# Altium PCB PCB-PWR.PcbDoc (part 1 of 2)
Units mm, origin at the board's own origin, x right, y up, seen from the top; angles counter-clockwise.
Board outline 90 x 60 mm, 4 copper layers (F.Cu, In1.Cu, In2.Cu, B.Cu); 66 components, 31 nets, 210 pads, 267 vias.
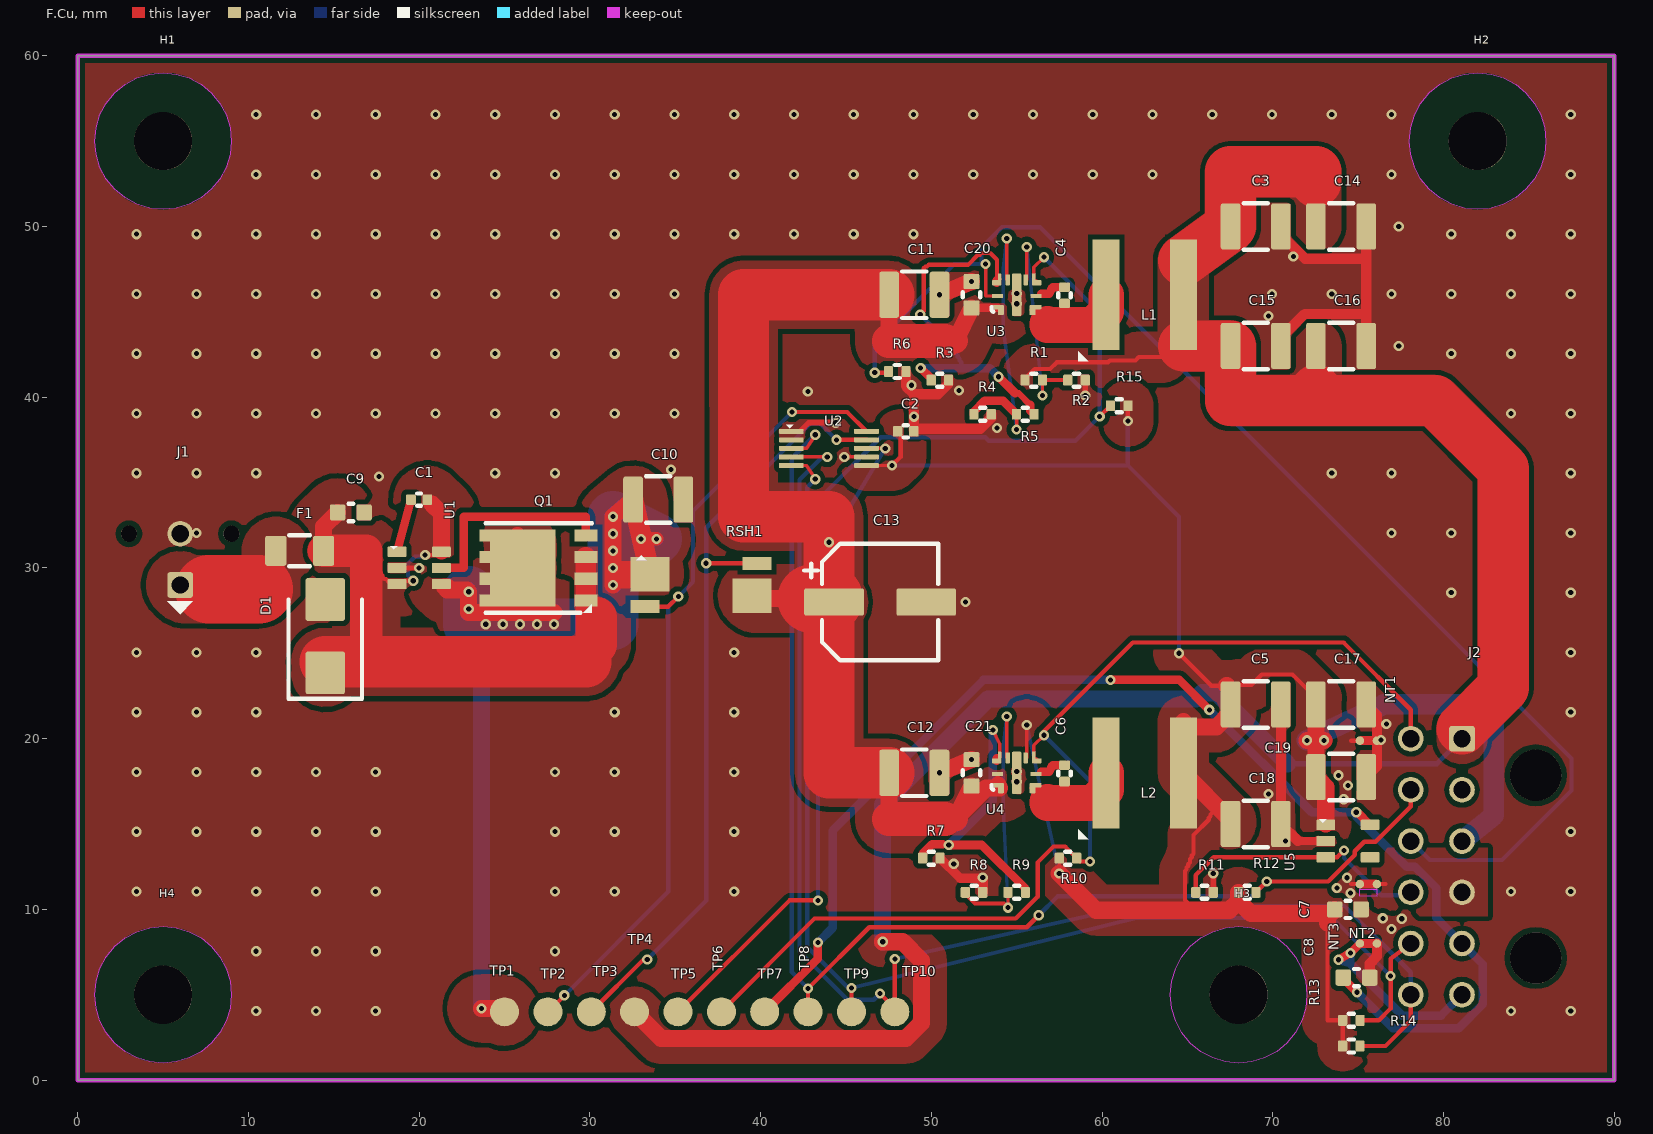
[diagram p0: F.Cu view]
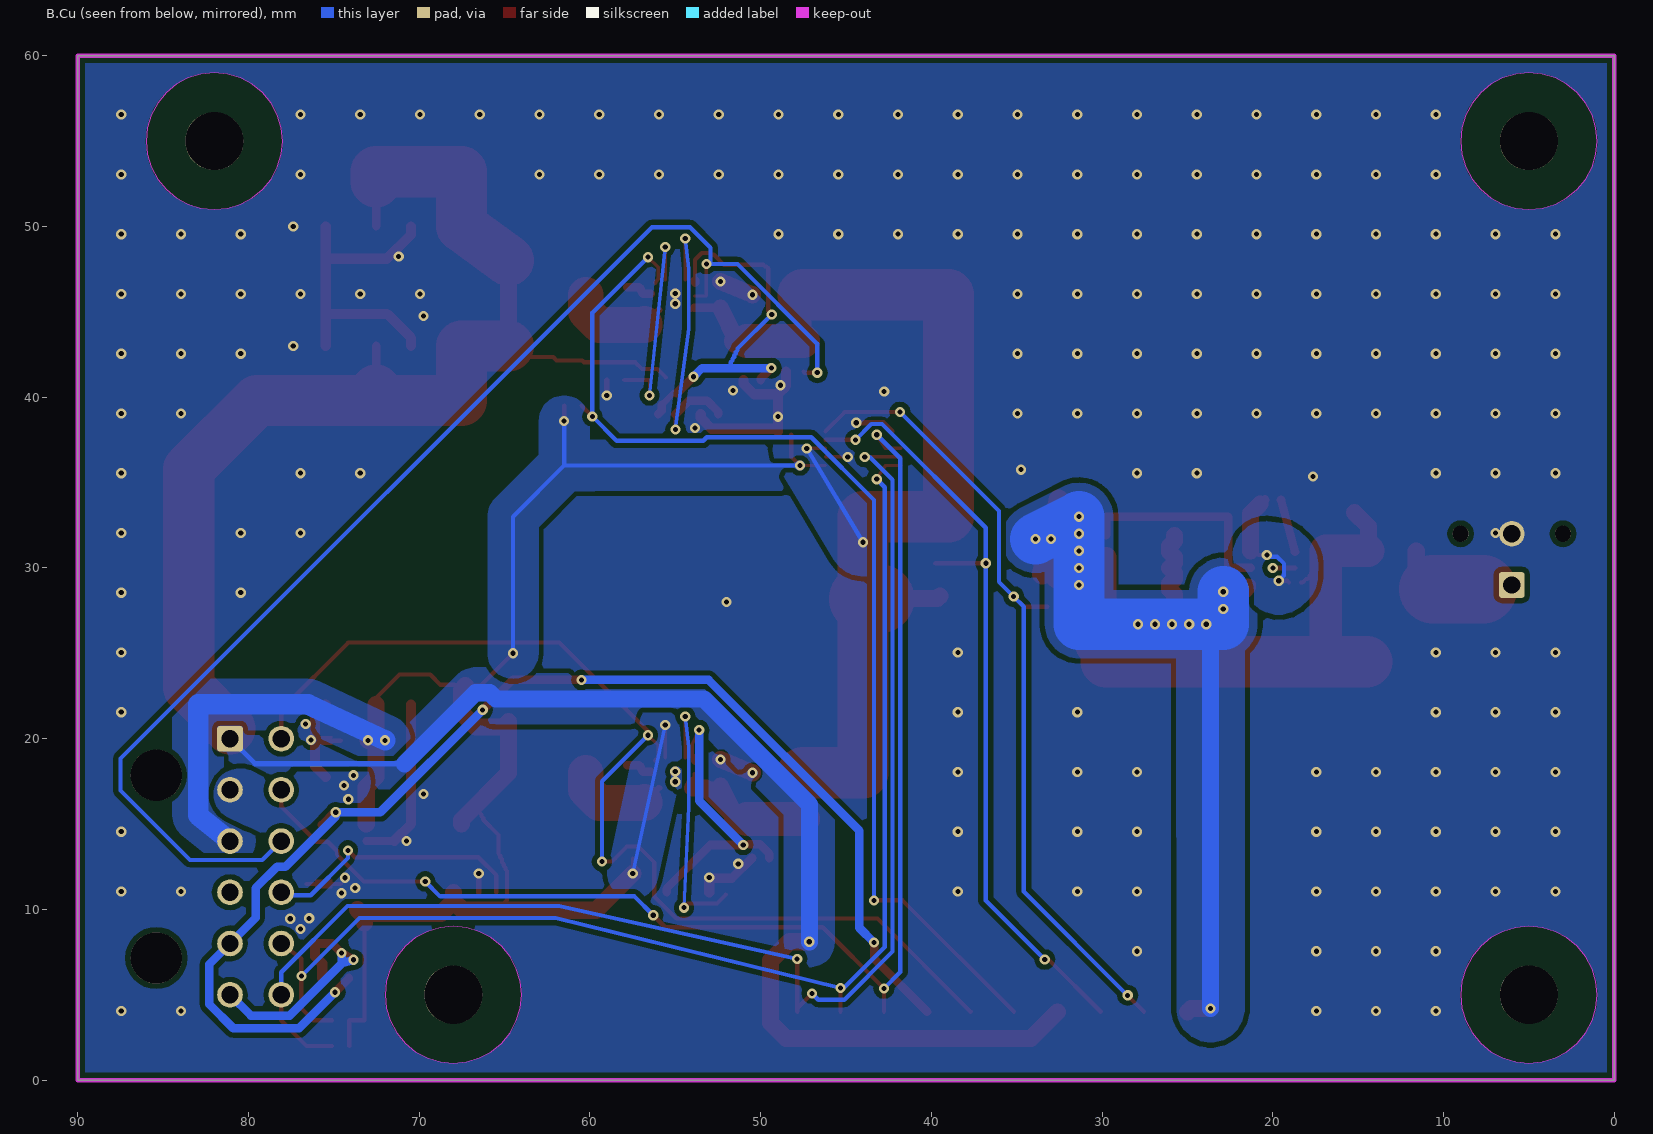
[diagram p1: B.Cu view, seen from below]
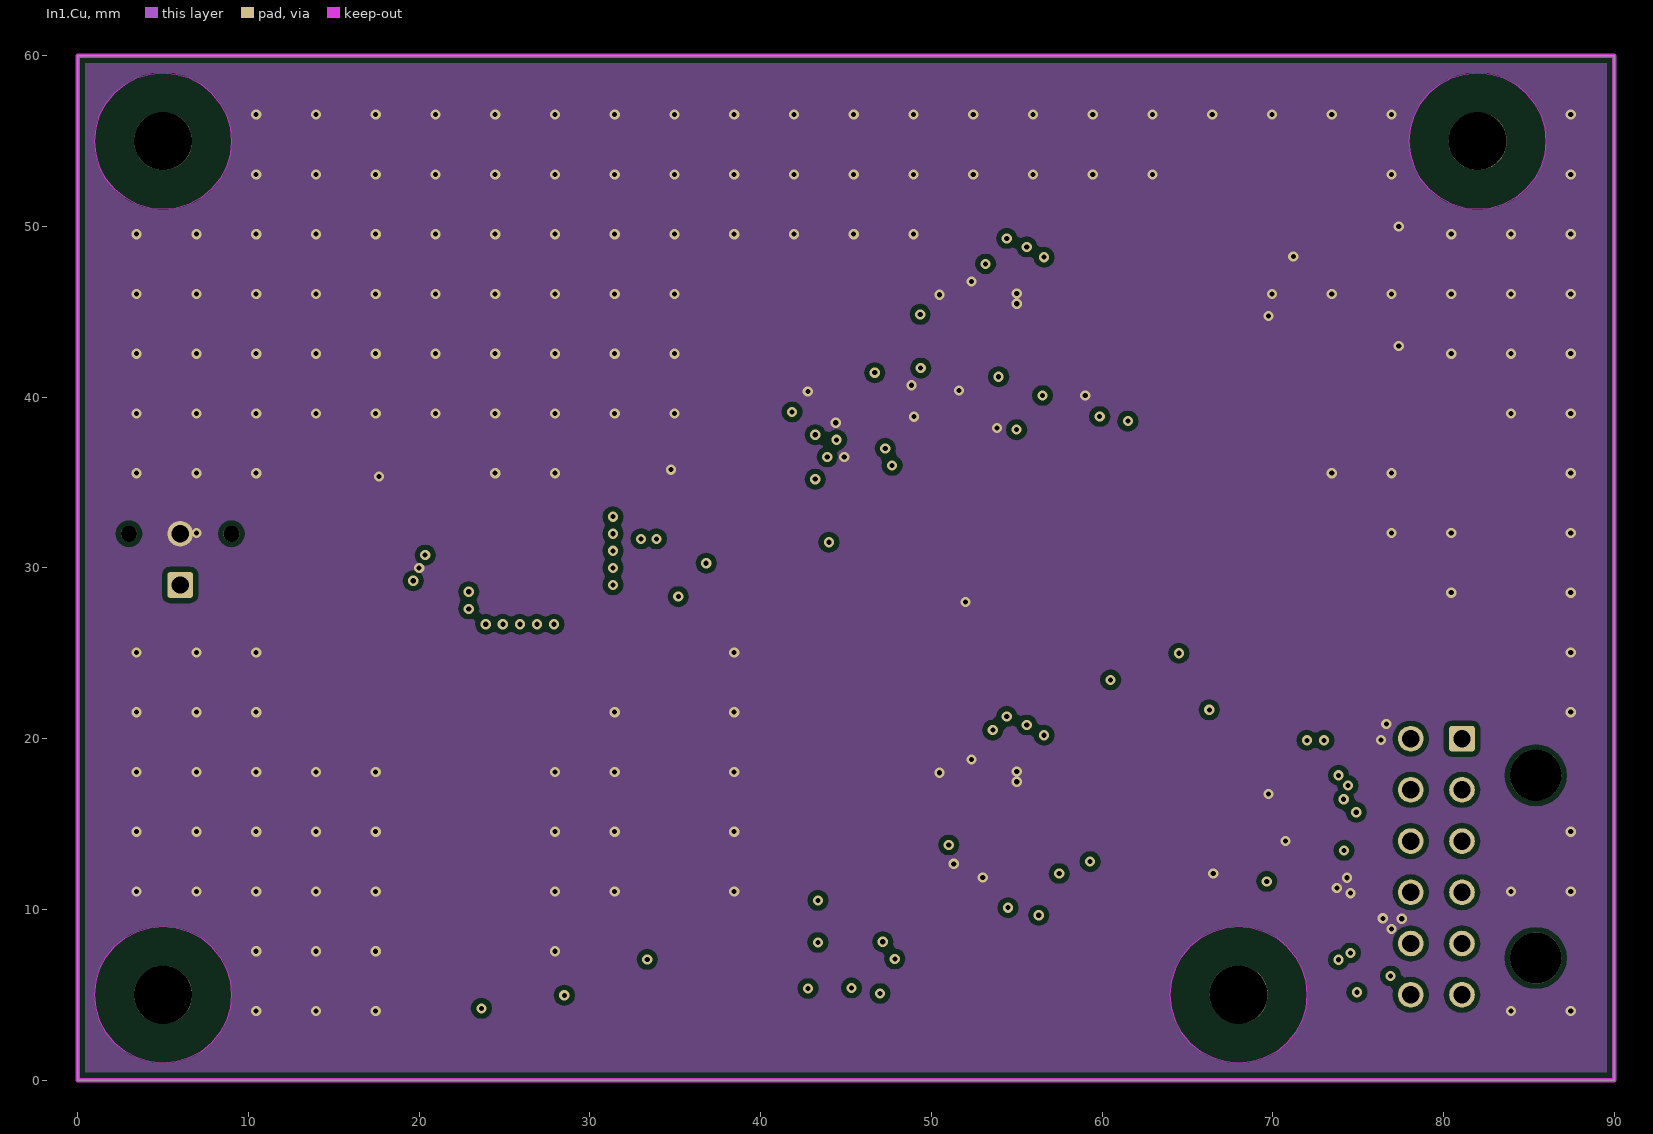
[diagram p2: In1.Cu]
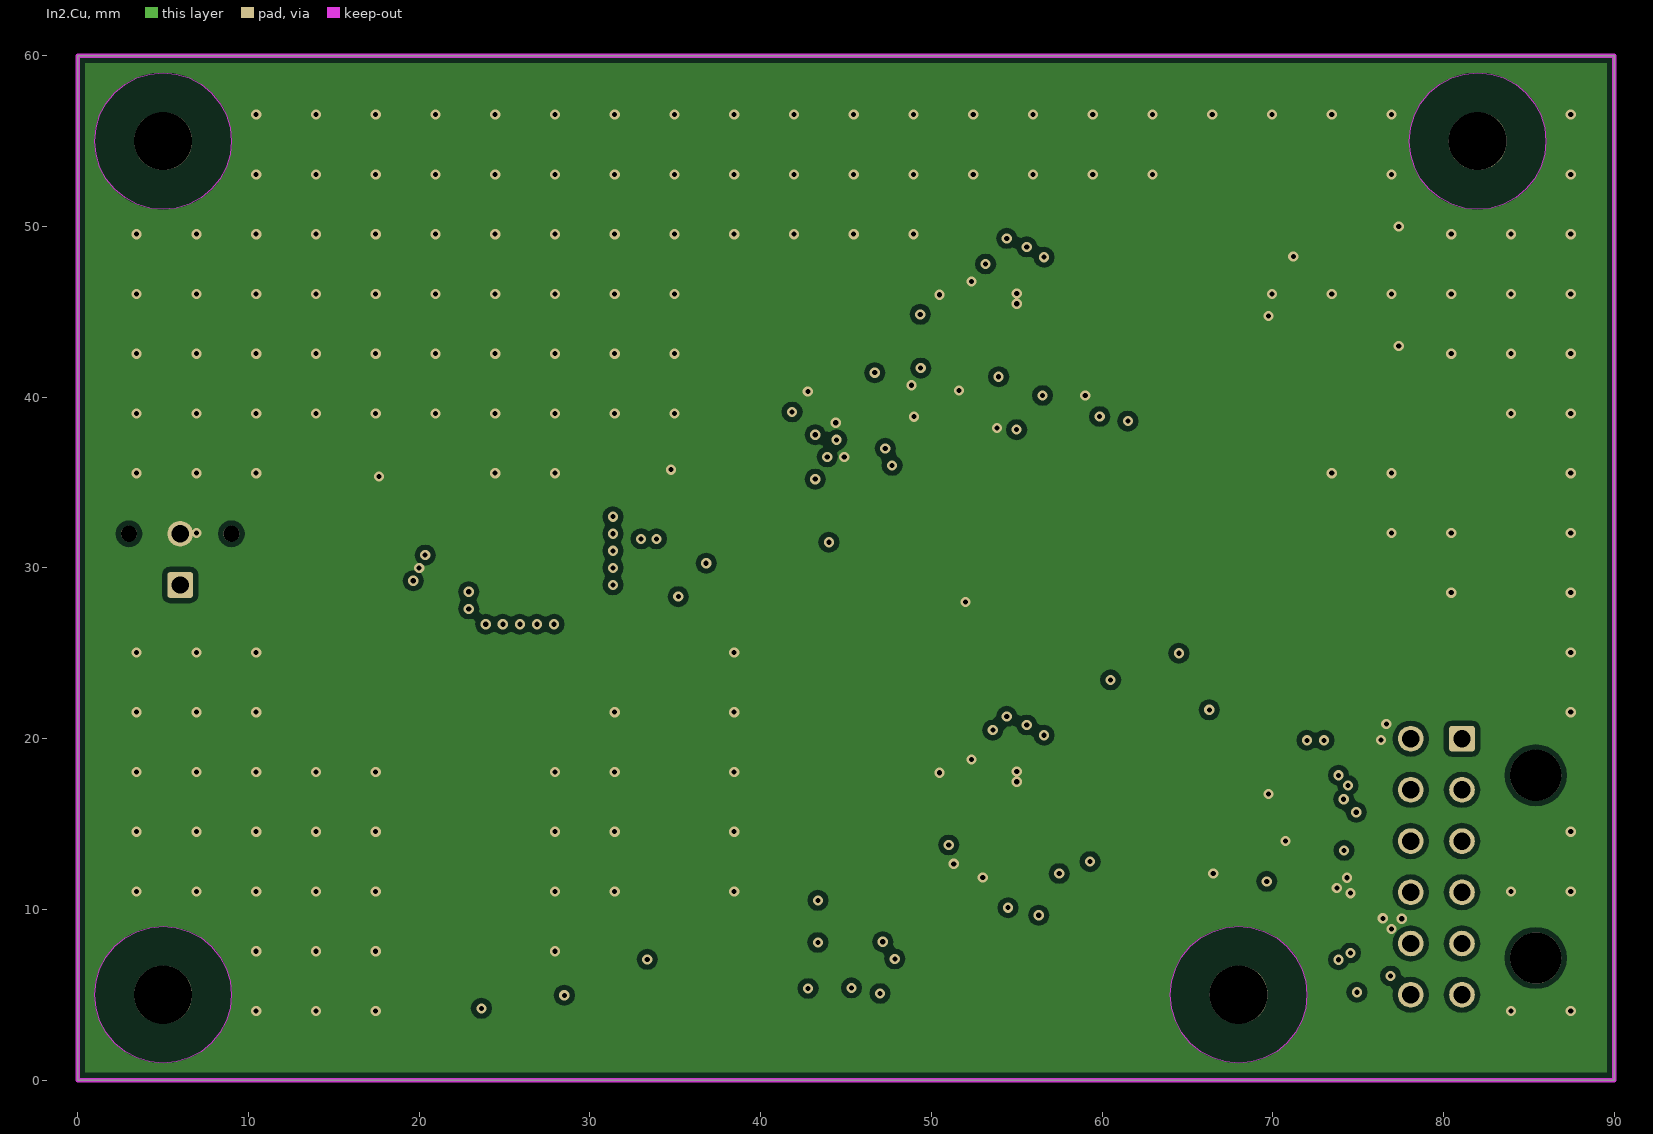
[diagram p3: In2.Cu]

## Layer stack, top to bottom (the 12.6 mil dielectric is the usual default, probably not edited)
F.Mask: solder mask 0.0102, Solder Resist, Dk 3.5
F.Cu: signal copper 0.0356
Dielectric 1: dielectric 0.32, FR-4, Dk 4.8
In1.Cu: signal copper 0.0356
Dielectric2: dielectric 0.32, FR-4, Dk 4.8
In2.Cu: signal copper 0.0356
Dielectric3: dielectric 0.32, FR-4, Dk 4.8
B.Cu: signal copper 0.0356
B.Mask: solder mask 0.0102, Solder Resist, Dk 3.5

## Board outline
0,0 0,60 90,60 90,0 0,0

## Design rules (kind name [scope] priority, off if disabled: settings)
Clearance "Clearence 2,3_PadClass" [InPadClass('Pad Class Clearance 2,3')] p1: gap=2.3 ignorepadtopadclearanceinfootprint=FALSE
Clearance "Clearence 0,3_Polygon" [InNamedPolygon('F.Cu-3V3_DIGITAL') OR InNamedPolygon('F.Cu-VBAT_SYS') OR InNamedPolygon('F.Cu-3V8_MODEM') OR InNamedPolygon('F.Cu-VBAT_PROTECTED') OR InNamedPolygon('F.Cu-VBAT_PROTECTED-1') OR InNamedPolygon('F.Cu-3V3_DIGITAL-1') OR InNamedPolygon('F.Cu-GND_MODEM') OR InNamedPolygon('F.Cu-3V3_DIGITAL-2') OR InNamedPolygon('F.Cu-GND_DIGITAL') OR InNamedPolygon('F.Cu-VBAT_FUSED') OR InNamedPolygon('F.Cu-3V8_MODEM-1') OR InNamedPolygon('F.Cu-GND_PWR') OR InNamedPolygon('F.Cu-3V3_DIGITAL-3') OR InNamedPolygon('F.Cu-VBAT_SYS-1') OR InNamedPolygon('F.Cu-VBAT_RAW') OR InNamedPolygon('B.Cu-3V3_DIGITAL') OR InNamedPolygon('B.Cu-3V3_DIGITAL-1') OR InNamedPolygon('B.Cu-GND_MODEM') OR InNamedPolygon('B.Cu-GND_PWR') OR InNamedPolygon('B.Cu-VBAT_PROTECTED') OR InNamedPolygon('B.Cu-VBAT_SYS') OR InNamedPolygon('B.Cu-3V8_MODEM') OR InNamedPolygon('B.Cu-3V3_DIGITAL-2') OR InNamedPolygon('B.Cu-VBAT_FUSED') OR InNamedPolygon('In1.Cu-GND_PWR') OR InNamedPolygon('In1.Cu-GND_PWR-1') OR InNamedPolygon('In1.Cu-GND_PWR-2') OR InNamedPolygon('In2.Cu-GND_PWR')] p2: gap=0.3 ignorepadtopadclearanceinfootprint=FALSE
HoleSize [All] p1: absolutevalues=TRUE maxlimit=3.4 minlimit=0.025 maxpercent=80.000 minpercent=20.000
MinimumSolderMaskSliver [All] p1: minsoldermaskwidth=0
PolygonConnect Polygon_In2.Cu-GND_PWR_ConnectDirect [IsNamedPolygon('In2.Cu-GND_PWR')] p1: connectstyle=Direct reliefconductorwidth=0.254 reliefentries=4 polygonreliefangle="90 Angle" airgapwidth=0.254
PolygonConnect Polygon_In1.Cu-GND_PWR-2_ConnectDirect [IsNamedPolygon('In1.Cu-GND_PWR-2')] p2: connectstyle=Direct reliefconductorwidth=0.254 reliefentries=4 polygonreliefangle="90 Angle" airgapwidth=0.254
PolygonConnect Polygon_In1.Cu-GND_PWR-1_ConnectDirect [IsNamedPolygon('In1.Cu-GND_PWR-1')] p3: connectstyle=Direct reliefconductorwidth=0.254 reliefentries=4 polygonreliefangle="90 Angle" airgapwidth=0.254
PolygonConnect Polygon_In1.Cu-GND_PWR_ConnectDirect [IsNamedPolygon('In1.Cu-GND_PWR')] p4: connectstyle=Direct reliefconductorwidth=0.254 reliefentries=4 polygonreliefangle="90 Angle" airgapwidth=0.254
PolygonConnect Polygon_B.Cu-VBAT_FUSED_ConnectDirect [IsNamedPolygon('B.Cu-VBAT_FUSED')] p5: connectstyle=Direct reliefconductorwidth=0.254 reliefentries=4 polygonreliefangle="90 Angle" airgapwidth=0.254
PolygonConnect Polygon_B.Cu-3V3_DIGITAL-2_ConnectDirect [IsNamedPolygon('B.Cu-3V3_DIGITAL-2')] p6: connectstyle=Direct reliefconductorwidth=0.254 reliefentries=4 polygonreliefangle="90 Angle" airgapwidth=0.254
PolygonConnect Polygon_B.Cu-3V8_MODEM_ConnectDirect [IsNamedPolygon('B.Cu-3V8_MODEM')] p7: connectstyle=Direct reliefconductorwidth=0.254 reliefentries=4 polygonreliefangle="90 Angle" airgapwidth=0.254
PolygonConnect Polygon_B.Cu-VBAT_SYS_ConnectDirect [IsNamedPolygon('B.Cu-VBAT_SYS')] p8: connectstyle=Direct reliefconductorwidth=0.254 reliefentries=4 polygonreliefangle="90 Angle" airgapwidth=0.254
PolygonConnect Polygon_B.Cu-VBAT_PROTECTED_ConnectDirect [IsNamedPolygon('B.Cu-VBAT_PROTECTED')] p9: connectstyle=Direct reliefconductorwidth=0.254 reliefentries=4 polygonreliefangle="90 Angle" airgapwidth=0.254
PolygonConnect Polygon_B.Cu-GND_PWR_ConnectDirect [IsNamedPolygon('B.Cu-GND_PWR')] p10: connectstyle=Direct reliefconductorwidth=0.254 reliefentries=4 polygonreliefangle="90 Angle" airgapwidth=0.254
PolygonConnect Polygon_B.Cu-GND_MODEM_ConnectDirect [IsNamedPolygon('B.Cu-GND_MODEM')] p11: connectstyle=Direct reliefconductorwidth=0.254 reliefentries=4 polygonreliefangle="90 Angle" airgapwidth=0.254
PolygonConnect Polygon_B.Cu-3V3_DIGITAL-1_ConnectDirect [IsNamedPolygon('B.Cu-3V3_DIGITAL-1')] p12: connectstyle=Direct reliefconductorwidth=0.254 reliefentries=4 polygonreliefangle="90 Angle" airgapwidth=0.254
PolygonConnect Polygon_B.Cu-3V3_DIGITAL_ConnectDirect [IsNamedPolygon('B.Cu-3V3_DIGITAL')] p13: connectstyle=Direct reliefconductorwidth=0.254 reliefentries=4 polygonreliefangle="90 Angle" airgapwidth=0.254
PolygonConnect Polygon_F.Cu-VBAT_RAW_ConnectDirect [IsNamedPolygon('F.Cu-VBAT_RAW')] p14: connectstyle=Direct reliefconductorwidth=0.254 reliefentries=4 polygonreliefangle="90 Angle" airgapwidth=0.254
PolygonConnect Polygon_F.Cu-VBAT_SYS-1_ConnectDirect [IsNamedPolygon('F.Cu-VBAT_SYS-1')] p15: connectstyle=Direct reliefconductorwidth=0.254 reliefentries=4 polygonreliefangle="90 Angle" airgapwidth=0.254
PolygonConnect Polygon_F.Cu-3V3_DIGITAL-3_ConnectDirect [IsNamedPolygon('F.Cu-3V3_DIGITAL-3')] p16: connectstyle=Direct reliefconductorwidth=0.254 reliefentries=4 polygonreliefangle="90 Angle" airgapwidth=0.254
PolygonConnect Polygon_F.Cu-GND_PWR_ConnectDirect [IsNamedPolygon('F.Cu-GND_PWR')] p17: connectstyle=Direct reliefconductorwidth=0.254 reliefentries=4 polygonreliefangle="90 Angle" airgapwidth=0.254
PolygonConnect Polygon_F.Cu-3V8_MODEM-1_ConnectDirect [IsNamedPolygon('F.Cu-3V8_MODEM-1')] p18: connectstyle=Direct reliefconductorwidth=0.254 reliefentries=4 polygonreliefangle="90 Angle" airgapwidth=0.254
PolygonConnect Polygon_F.Cu-VBAT_FUSED_ConnectDirect [IsNamedPolygon('F.Cu-VBAT_FUSED')] p19: connectstyle=Direct reliefconductorwidth=0.254 reliefentries=4 polygonreliefangle="90 Angle" airgapwidth=0.254
PolygonConnect Polygon_F.Cu-GND_DIGITAL_ConnectDirect [IsNamedPolygon('F.Cu-GND_DIGITAL')] p20: connectstyle=Direct reliefconductorwidth=0.254 reliefentries=4 polygonreliefangle="90 Angle" airgapwidth=0.254
PolygonConnect Polygon_F.Cu-3V3_DIGITAL-2_ConnectDirect [IsNamedPolygon('F.Cu-3V3_DIGITAL-2')] p21: connectstyle=Direct reliefconductorwidth=0.254 reliefentries=4 polygonreliefangle="90 Angle" airgapwidth=0.254
PolygonConnect Polygon_F.Cu-GND_MODEM_ConnectDirect [IsNamedPolygon('F.Cu-GND_MODEM')] p22: connectstyle=Direct reliefconductorwidth=0.254 reliefentries=4 polygonreliefangle="90 Angle" airgapwidth=0.254
PolygonConnect Polygon_F.Cu-3V3_DIGITAL-1_ConnectDirect [IsNamedPolygon('F.Cu-3V3_DIGITAL-1')] p23: connectstyle=Direct reliefconductorwidth=0.254 reliefentries=4 polygonreliefangle="90 Angle" airgapwidth=0.254
PolygonConnect Polygon_F.Cu-VBAT_PROTECTED-1_ConnectDirect [IsNamedPolygon('F.Cu-VBAT_PROTECTED-1')] p24: connectstyle=Direct reliefconductorwidth=0.254 reliefentries=4 polygonreliefangle="90 Angle" airgapwidth=0.254
PolygonConnect Polygon_F.Cu-VBAT_PROTECTED_ConnectDirect [IsNamedPolygon('F.Cu-VBAT_PROTECTED')] p25: connectstyle=Direct reliefconductorwidth=0.254 reliefentries=4 polygonreliefangle="90 Angle" airgapwidth=0.254
PolygonConnect Polygon_F.Cu-3V8_MODEM_ConnectDirect [IsNamedPolygon('F.Cu-3V8_MODEM')] p26: connectstyle=Direct reliefconductorwidth=0.254 reliefentries=4 polygonreliefangle="90 Angle" airgapwidth=0.254
PolygonConnect Polygon_F.Cu-VBAT_SYS_ConnectDirect [IsNamedPolygon('F.Cu-VBAT_SYS')] p27: connectstyle=Direct reliefconductorwidth=0.254 reliefentries=4 polygonreliefangle="90 Angle" airgapwidth=0.254
PolygonConnect Polygon_F.Cu-3V3_DIGITAL_ConnectDirect [IsNamedPolygon('F.Cu-3V3_DIGITAL')] p28: connectstyle=Direct reliefconductorwidth=0.254 reliefentries=4 polygonreliefangle="90 Angle" airgapwidth=0.254
RoutingVias [All] p1: holewidth=0.711 width=1.27 viastyle="Through Hole" minholewidth=0.711 minwidth=1.27 maxholewidth=0.711 maxwidth=1.27
SilkToSilkClearance [All] p1: silktosilkclearance=0
SilkToSolderMaskClearance [IsPad] p1: minsilkscreentomaskgap=0 clearancetoexposedcopper=TRUE
SolderMaskExpansion [All] p1: expansion=0 istentingtop=FALSE
Width [All] p1: maxlimit=10 minlimit=0.2 preferedwidth=0.25 minimp=50.000000 maximp=50.000000 favimp=50.000000
26 further rules are at their usual default settings.

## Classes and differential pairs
pad class "Pad Class Clearance 2,3": H1-Un1 H2-Un1 H3-Un1 H4-Un1

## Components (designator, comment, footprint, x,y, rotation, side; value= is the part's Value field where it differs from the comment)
C1 "Comment" C_0402_1005Metric 20,34 r0 top value="100 nF 25 V X7R CGA2B3X7R1E104K050BB"
C2 "Comment" C_0402_1005Metric 48.5,38 r0 top value="100 nF 25 V X7R CGA2B3X7R1E104K050BB"
C3 "Comment" C_1210_3225Metric 69,50 r0 top value="22 uF 25 V X7R CGA6P3X7R1E226M250AB"
C4 "Comment" C_0402_1005Metric 57.8,45.97 r270 top value="100 nF 25 V X7R CGA2B3X7R1E104K050BB"
C5 "Comment" C_1210_3225Metric 69,22 r0 top value="22 uF 25 V X7R CGA6P3X7R1E226M250AB"
C6 "Comment" C_0402_1005Metric 57.8,17.97 r270 top value="100 nF 25 V X7R CGA2B3X7R1E104K050BB"
C7 "Comment" C_0603_1608Metric 74.4,10 r0 top value="2.2 uF 10 V X7R CGA3E1X7R1A225K080AC"
C8 "Comment" C_0603_1608Metric 74.9,6 r0 top value="2.2 uF 10 V X7R CGA3E1X7R1A225K080AC"
C9 "Comment" C_0603_1608Metric 16,33.25 r0 top value="100 nF 50 V X7R CGA3E2X7R1H104K080AA"
C10 "Comment" C_1210_3225Metric 34,34 r0 top value="4.7 uF 50 V X7R CGA6P3X7R1H475K250AB"
C11 "Comment" C_1210_3225Metric 49,46 r0 top value="4.7 uF 50 V X7R CGA6P3X7R1H475K250AB"
C12 "Comment" C_1210_3225Metric 49,18 r0 top value="4.7 uF 50 V X7R CGA6P3X7R1H475K250AB"
C13 "Comment" CP_Elec_6.3x7.7 47,28 r0 top value="100 uF 35 V hybrid EEH-ZK1V101XP"
C14 "Comment" C_1210_3225Metric 74,50 r0 top value="22 uF 25 V X7R CGA6P3X7R1E226M250AB"
C15 "Comment" C_1210_3225Metric 69,43 r0 top value="22 uF 25 V X7R CGA6P3X7R1E226M250AB"
C16 "Comment" C_1210_3225Metric 74,43 r0 top value="22 uF 25 V X7R CGA6P3X7R1E226M250AB"
C17 "Comment" C_1210_3225Metric 74,22 r0 top value="22 uF 25 V X7R CGA6P3X7R1E226M250AB"
C18 "Comment" C_1210_3225Metric 69,15 r0 top value="22 uF 25 V X7R CGA6P3X7R1E226M250AB"
C19 "Comment" C_1210_3225Metric 74,17.75 r0 top value="22 uF 25 V X7R CGA6P3X7R1E226M250AB"
C20 "Comment" C_0603_1608Metric 52.35,46 r90 top value="100 nF 50 V X7R CGA3E2X7R1H104K080AA"
C21 "Comment" C_0603_1608Metric 52.35,18 r90 top value="100 nF 50 V X7R CGA3E2X7R1H104K080AA"
D1 "Comment" D_SMB 14.5,26 r90 top value="SMBJ18A CANDIDATE"
F1 "Comment" Fuse_1206_3216Metric 13,31 r0 top value=0451008.MRL
H1 "Comment" MountingHole_M3_3.4_EVT 5,55 r0 top value=M3_CLEARANCE_NPTH_3.4
H2 "Comment" MountingHole_M3_3.4_EVT 82,55 r0 top value=M3_CLEARANCE_NPTH_3.4
H3 "Comment" MountingHole_M3_3.4_EVT 68,5 r0 top value=M3_CLEARANCE_NPTH_3.4
H4 "Comment" MountingHole_M3_3.4_EVT 5,5 r0 top value=M3_CLEARANCE_NPTH_3.4
J1 "Comment" Molex_43045-0213_MicroFit-2_Vertical 6,32 r0 top value=43045-0213
J2 "Comment" Molex_43045-1202_MicroFit-12_RA 81.08,20 r270 top value=43045-1202
L1 "Comment" Coilcraft_XAL7030_472 62.5,46 r180 top value=XAL7030-472MEC
L2 "Comment" Coilcraft_XAL7030_472 62.5,18 r180 top value=XAL7030-472MEC
NT1 "Comment" NETTIE-2_SMD_PAD0.5MM 75.6,19.88 r0 top net-tie value="2-pad copper net tie NET_TIE_COPPER_REV_A"
NT2 "Comment" NETTIE-2_SMD_PAD0.5MM 75.6,11.48 r180 top net-tie value="2-pad copper net tie NET_TIE_COPPER_REV_A"
NT3 "Comment" NETTIE-2_SMD_PAD0.5MM 75.6,8 r0 top net-tie value="2-pad copper net tie NET_TIE_COPPER_REV_A"
Q1 "Comment" CSD18540Q5B_DNK 27,30 r0 top value=CSD18540Q5B
R1 "Comment" R_0402_1005Metric 56,41 r0 top value="100 kOhm 0.1% ERA-2AEB104X"
R2 "Comment" R_0402_1005Metric 58.5,41 r0 top value="35.7 kOhm 0.1% ERA-2AEB3572X"
R3 "Comment" R_0402_1005Metric 50.5,41 r0 top value="86.6 kOhm 0.1% ERA-2AEB8662X"
R4 "Comment" R_0402_1005Metric 53,39 r0 top value="0 ohm ERJ-2GE0R00X"
R5 "Comment" R_0402_1005Metric 55.5,39 r0 top value="0 ohm ERJ-2GE0R00X"
R6 "Comment" R_0402_1005Metric 48,41.5 r0 top value="100 kOhm 1% ERJ-2RKF1003X"
R7 "Comment" R_0402_1005Metric 50,13 r0 top value="86.6 kOhm 0.1% ERA-2AEB8662X"
R8 "Comment" R_0402_1005Metric 52.5,11 r0 top value="0 ohm ERJ-2GE0R00X"
R9 "Comment" R_0402_1005Metric 55,11 r0 top value="0 ohm ERJ-2GE0R00X"
R10 "Comment" R_0402_1005Metric 58,13 r0 top value="10 kOhm 1% ERJ-2RKF1002X"
R11 "Comment" R_0402_1005Metric 66,11 r0 top value="100 kOhm 1% ERJ-2RKF1003X"
R12 "Comment" R_0402_1005Metric 68.5,11 r0 top value="10 kOhm 1% ERJ-2RKF1002X"
R13 "Comment" R_0402_1005Metric 74.6,3.5 r0 top value="4.7 kOhm 1% ERJ-2RKF4701X"
R14 "Comment" R_0402_1005Metric 74.6,2 r0 top value="4.7 kOhm 1% ERJ-2RKF4701X"
R15 "Comment" R_0402_1005Metric 61,39.5 r0 top value="10 kOhm 1% ERJ-2RKF1002X"
RSH1 "Comment" Vishay_WSK2512_4T_T1.19mm 36.5,29 r0 top value=WSK2512R0100FEA
TP1 "Comment" TestPoint_DFT_1.7mm_NoPaste 25,4 r0 top value="TP_VBAT_PROTECTED DFT_PAD_1P70_NOPASTE_REV_A"
TP2 "Comment" TestPoint_DFT_1.7mm_NoPaste 27.54,4 r0 top value="TP_SHUNT_SRC DFT_PAD_1P70_NOPASTE_REV_A"
TP3 "Comment" TestPoint_DFT_1.7mm_NoPaste 30.08,4 r0 top value="TP_SHUNT_LOAD DFT_PAD_1P70_NOPASTE_REV_A"
TP4 "Comment" TestPoint_DFT_1.7mm_NoPaste 32.62,4 r0 top value="TP_3V8 DFT_PAD_1P70_NOPASTE_REV_A"
TP5 "Comment" TestPoint_DFT_1.7mm_NoPaste 35.16,4 r0 top value="TP_PG_3V8 DFT_PAD_1P70_NOPASTE_REV_A"
TP6 "Comment" TestPoint_DFT_1.7mm_NoPaste 37.7,4 r0 top value="TP_PWR_GOOD DFT_PAD_1P70_NOPASTE_REV_A"
TP7 "Comment" TestPoint_DFT_1.7mm_NoPaste 40.24,4 r0 top value="TP_1V8 DFT_PAD_1P70_NOPASTE_REV_A"
TP8 "Comment" TestPoint_DFT_1.7mm_NoPaste 42.78,4 r0 top value="TP_FAULT DFT_PAD_1P70_NOPASTE_REV_A"
TP9 "Comment" TestPoint_DFT_1.7mm_NoPaste 45.32,4 r0 top value="TP_SCL DFT_PAD_1P70_NOPASTE_REV_A"
TP10 "Comment" TestPoint_DFT_1.7mm_NoPaste 47.86,4 r0 top value="TP_SDA DFT_PAD_1P70_NOPASTE_REV_A"
U1 "Comment" TI_DBV0006A_SOT23-6 20,30 r0 top value=LM74700QDBVRQ1
U2 "Comment" TI_DGS0010A_VSSOP10 44,37 r0 top value=INA226AIDGSR
U3 "Comment" LMR60440_RAK0009A 55,46 r90 top value=LMR604403SRAKR
U4 "Comment" LMR60440_RAK0009A 55,18 r90 top value=LMR604403SRAKR
U5 "Comment" TI_DBV0005A_SOT23-5 74.4,14 r0 top value=TPS7A2018PDBVR

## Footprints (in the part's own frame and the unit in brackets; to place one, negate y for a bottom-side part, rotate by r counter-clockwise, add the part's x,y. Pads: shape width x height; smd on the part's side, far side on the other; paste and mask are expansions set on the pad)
C_0402_1005Metric [mm]
  rrect25% 0.56x0.62 smd mask+0: 1(-0.48,0) 2(0.48,0)
  silkscreen extent -0.11,-0.36 0.11,0.36
C_0603_1608Metric [mm]
  rrect25% 0.9x0.95 smd mask+0: 1(-0.775,0) 2(0.775,0)
  silkscreen extent -0.14,-0.51 0.14,0.51
C_1210_3225Metric [mm]
  rrect22% 1.15x2.7 smd mask+0: 1(-1.475,0) 2(1.475,0)
  silkscreen extent -0.71,-1.36 0.71,1.36
Coilcraft_XAL7030_472 [mm]
  rect 1.58x6.5 smd mask+0: 1(2.26,0) 2(-2.26,0)
  silkscreen extent 3.3,3.3 3.9,3.9
CP_Elec_6.3x7.7 [mm]
  rrect16% 3.5x1.6 smd mask+0: 1(-2.7,0) 2(2.7,0)
  silkscreen extent -4.44,-3.41 3.41,3.41
CSD18540Q5B_DNK [mm]
  rect 1.372x0.71 smd paste-1.372 mask+0: 1(2.77,-1.905) 2(2.77,-0.635) 3(2.77,0.635) 4(2.77,1.905)
  rect 4.44x0.71 smd paste-4.44 mask+0: 5(-1.236,1.905) 6(-1.236,0.635) 7(-1.236,-0.635) 8(-1.236,-1.905)
  rect 3.85x0.56 smd paste-3.85 mask+0: 5(-0.941,-1.27) 5(-0.941,0) 5(-0.941,1.27)
  rect 0.766x0.508 on Top Paste mask-0.766: Un1(-2.91,1.905) Un2(-2.91,0.635) Un3(-2.91,-0.635) Un4(-2.91,-1.905)
  rect 1.294x0.746 on Top Paste mask-1.294: Un5(-1.594,1.569) Un6(-1.594,0.523) Un7(-1.594,-0.523) Un8(-1.594,-1.569) Un9(0.05,1.569) Un10(0.05,0.523) Un11(0.05,-0.523) Un12(0.05,-1.569)
  rect 1.072x0.562 on Top Paste mask-1.072: Un13(2.758,1.905) Un14(2.758,0.635) Un15(2.758,-0.635) Un16(2.758,-1.905)
  silkscreen extent -3.12,-2.62 3.12,2.62
D_SMB [mm]
  rrect11% 2.5x2.3 smd mask+0: 1(-2.15,0) 2(2.15,0)
  silkscreen extent -3.66,-2.15 2.15,2.15
Fuse_1206_3216Metric [mm]
  rrect20% 1.25x1.75 smd mask+0: 1(-1.4,0) 2(1.4,0)
  silkscreen extent -0.6,-0.91 0.6,0.91
LMR60440_RAK0009A [mm]
  rrect29% 0.6x0.345 smd paste-0.6 mask+0.05: 1(-0.9,0.927) 3(-0.9,-0.927)
  rrect40% 0.25x0.695 smd paste-0.695 mask+0.05: 1(-0.725,1.102) 3(-0.725,-1.102)
  rrect36% 2.5x0.55 smd paste-2.5 mask-2.5: 2(0,0)
  rrect40% 0.25x0.65 smd mask+0.05: 4(-0.075,-1.125) 9(-0.075,1.125)
  rrect33% 0.3x0.55 smd mask+0.05: 5(0.7,-1.175) 8(0.7,1.175)
  rrect50% 0.7x0.2 smd mask+0.05: 5(0.9,-1) 8(0.9,1)
  rrect40% 0.65x0.25 smd mask+0.05: 6(0.875,-0.525) 7(0.875,0.525)
  rrect29% 0.56x0.345 on Top Paste mask-0.56: Un1(-0.92,0.927) Un2(-0.92,-0.927)
  rrect48% 0.21x0.695 on Top Paste mask-0.695: Un3(-0.745,1.102) Un4(-0.745,-1.102)
  rrect24% 1.1x0.41 on Top Paste mask-1.1: Un5(-0.65,0)
  rect 0.01x0.01 on Top Solder paste-0.01 mask-0.01: Un6(0,0)
  rrect33% 1.1x0.3 on Top Paste mask-1.1: Un7(0.65,0)
  silkscreen extent -1,1.38 -0.72,1.48
Molex_43045-0213_MicroFit-2_Vertical [mm]
  rrect20% 1.5x1.5 hole 1.02 paste-2539.97 mask+0: 1(0,-3)
  round 1.5 hole 1.02 paste-2539.97 mask+0: 2(0,0)
  round 0.94 hole 0.94 paste-2539.97 mask+0: Un1(-3,0) Un2(3,0)
  silkscreen extent -0.75,-4.7 0.75,-3.95
Molex_43045-1202_MicroFit-12_RA [mm]
  rrect20% 1.5x1.5 hole 1.02 paste-2539.97 mask+0: 1(0,0)
  round 1.5 hole 1.02 paste-2539.97 mask+0: 2(3,0) 3(6,0) 4(9,0) 5(12,0) 6(15,0) 7(0,-3) 8(3,-3) 9(6,-3) 10(9,-3) 11(12,-3) 12(15,-3)
  round 3 hole 3 paste-2539.97 mask+0: Un1(2.15,4.32) Un2(12.85,4.32)
MountingHole_M3_3.4_EVT [mm]
  round 3.4 hole 3.4 paste-2539.97 mask+0: Un1(0,0)
NETTIE-2_SMD_PAD0.5MM [mm]
  round 0.5 smd: 1(-0.5,0) 2(0.5,0)
  F.Cu region: 0.5,-0.25 -0.5,-0.25 -0.5,0.25 0.5,0.25
R_0402_1005Metric [mm]
  rrect25% 0.54x0.64 smd mask+0: 1(-0.51,0) 2(0.51,0)
  silkscreen extent -0.15,-0.38 0.15,0.38
TestPoint_DFT_1.7mm_NoPaste [mm]
  round 1.7 smd paste-1.7 mask+0.1: 1(0,0)
TI_DBV0005A_SOT23-5 [mm]
  rrect17% 1.1x0.6 smd mask+0.07: 1(-1.3,0.95) 2(-1.3,0) 3(-1.3,-0.95) 4(1.3,-0.95) 5(1.3,0.95)
  silkscreen extent -1.68,1.08 -1.28,1.28
TI_DBV0006A_SOT23-6 [mm]
  rrect17% 1.1x0.6 smd mask+0.07: 1(-1.3,0.95) 2(-1.3,0) 3(-1.3,-0.95) 4(1.3,-0.95) 5(1.3,0) 6(1.3,0.95)
  silkscreen extent -1.68,1.08 -1.28,1.28
TI_DGS0010A_VSSOP10 [mm]
  rrect33% 1.45x0.3 smd mask+0.05: 1(-2.2,1) 2(-2.2,0.5) 3(-2.2,0) 4(-2.2,-0.5) 5(-2.2,-1) 6(2.2,-1) 7(2.2,-0.5) 8(2.2,0) 9(2.2,0.5) 10(2.2,1)
  silkscreen extent -2.5,1.18 -2.1,1.38
Vishay_WSK2512_4T_T1.19mm [mm]
  rect 2.29x2.03 smd mask+0: 1(-2.985,0.635) 2(2.985,-0.635)
  rect 1.7x0.76 smd mask+0: 3(-3.28,-1.27) 4(3.28,1.27)
  silkscreen extent -3.8,1.45 -3.2,1.75

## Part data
C1 C2 C4 C6: library part C_0402_1005Metric, "DIONEA_PCB_PWR_REV_A"
C3 C5 C10 C11 C12 C14 C15 C16 C17 C18 C19: library part C_1210_3225Metric, "DIONEA_PCB_PWR_REV_A"
C7 C8 C9 C20 C21: library part C_0603_1608Metric, "DIONEA_PCB_PWR_REV_A"
C13: library part CP_Elec_6.3x7.7, "DIONEA_PCB_PWR_REV_A"
D1: library part D_SMB, "DIONEA_PCB_PWR_REV_A"
F1: library part Fuse_1206_3216Metric, "DIONEA_PCB_PWR_REV_A"
H1 H2 H3 H4: library part MountingHole_M3_3.4_EVT, "DIONEA_PCB_PWR_EVT_MOUNT"
J1: library part Molex_43045-0213_MicroFit-2_Vertical, "DIONEA_PCB_PWR_REV_A"
J2: library part Molex_43045-1202_MicroFit-12_RA, "DIONEA_PCB_PWR_REV_A"
L1 L2: library part Coilcraft_XAL7030_472, "DIONEA_PCB_PWR_REV_A"
NT1 NT2 NT3: library part NetTie-2_SMD_Pad0.5mm, "DIONEA_PCB_PWR_REV_A"
Q1: library part CSD18540Q5B_DNK, "DIONEA_PCB_PWR_REV_A"
R1 R2 R3 R4 R5 R6 R7 R8 R9 R10 R11 R12 R13 R14 R15: library part R_0402_1005Metric, "DIONEA_PCB_PWR_REV_A"
RSH1: library part Vishay_WSK2512_4T_T1.19mm, "DIONEA_PCB_PWR_REV_A"
TP1 TP2 TP3 TP4 TP5 TP6 TP7 TP8 TP9 TP10: library part TestPoint_DFT_1.7mm_NoPaste, "DIONEA_PCB_PWR_REV_A"
U1: library part TI_DBV0006A_SOT23-6, "DIONEA_PCB_PWR_REV_A"
U2: library part TI_DGS0010A_VSSOP10, "DIONEA_PCB_PWR_REV_A"
U3 U4: library part LMR60440_RAK0009A, "DIONEA_PCB_PWR_REV_A"
U5: library part TI_DBV0005A_SOT23-5, "DIONEA_PCB_PWR_REV_A"

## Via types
v1: diameter 0.6, hole 0.3, F.Cu to B.Cu, tented both sides, 267 vias

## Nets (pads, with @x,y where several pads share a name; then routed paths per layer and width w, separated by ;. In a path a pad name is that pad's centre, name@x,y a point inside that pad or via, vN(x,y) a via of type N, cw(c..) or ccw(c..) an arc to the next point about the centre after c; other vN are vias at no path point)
1V8_MIC: C8.1 J2.5 TP7.1 U5.5 | length 75.5
  F.Cu w0.5: TP7.1@40.24,4 43.353,7.113 v1(43.353,8.061) ; v1(60.496,23.439) 64.528,23.439 v1(66.282,21.686) ; C8.1@74.125,6 74.125,5.947 v1(74.926,5.146) ; v1(74.884,15.685) 74.965,15.685 U5.5@75.7,14.95
  B.Cu w0.5: v1(43.353,8.061) 44.219,8.927 44.219,14.61 53.048,23.439 v1(60.496,23.439) ; v1(66.282,21.686) 72.282,15.685 v1(74.884,15.685) 74.884,15.448 77.832,12.5 78.325,12.5 79.58,11.245 79.58,9.5 J2.5@81.08,8 82.287,6.793 82.287,4.433 80.895,3.042 77.03,3.042 v1(74.926,5.146)
3V3_DIGITAL: C2.1 C5.1 C7.1 C17.1 C18.1 C19.1 J2.3 L2.2 R10.1 R12.1 R13.1 R14.1 R15.2 U2.6 U4.6 U5.1 | length 130.3
  F.Cu w0.2: U2.6@46.2,36 v1(47.7,36) ; U4.6@55.585,18.875 v1(55.585,20.8) ; v1(57.49,12.1) R10.1@57.49,13
  F.Cu w0.25: v1(47.7,36) 48.2,36.5 C2.1@48.2,37.8 ; v1(61.51,38.6) R15.2@61.51,39.5 ; v1(64.5,25) 66.4,23.1 C5.1@67.3,23.1 ; 66.55,15.75 66.35,15.55 66.35,15.45 66.25,15.35 66.25,15.25 65.35,14.35 65.35,13.25 65.25,13.15 65.25,13.05 65.15,12.95 65.15,12.75 65.05,12.65 65.05,12.55 64.95,12.45 64.95,12.35 64.85,12.25 64.85,10.55 65.05,10.35 66.25,10.35 66.45,10.15 67.15,10.15 ; C5.1@67.95,23.15 68.75,23.15 69.35,23.75 71.15,23.75 C17.1@72.55,22.35 ; C7.1@73.625,9.7 73.2,9.2 73.2,3.5 R13.1@74.09,3.5 R14.1@74.09,2
  F.Cu w0.601: U5.1@73.1,14.95 U5.1@73.1,15.002
  F.Cu w1: v1(57.49,12.1) 59.642,9.947 67.454,9.947 67.99,10.483 ; C5.1@67.3,23.1 67.525,22.875 C5.1@67.525,22 67.525,21.512 66.696,20.684 65.086,20.684 64.76,21.01 L2.2@64.76,18 67.525,15.235 C18.1@67.525,15 ; R12.1@67.99,11 67.99,10.483 ; v1(72,19.9) v1(73,19.9) ; C17.1@72.525,22 C19.1@72.525,17.75 73.1,17.175 U5.1@73.1,15.002 ; 73.2,9.2 C7.1@73.2,9.762 ; C7.1@73.625,10 73.387,9.762 C7.1@73.2,9.762 ; 67.99,10.483 68.711,9.762 C7.1@73.2,9.762
  B.Cu w0.2: v1(55.585,20.8) v1(57.49,12.1)
  B.Cu w0.25: v1(47.7,36) 61.51,36 ; v1(61.51,38.6) 61.51,36 ; v1(64.5,25) 64.5,33 61.51,36
  B.Cu w1.2: v1(72,19.9) 76.5,22 82.95,22 82.95,15.5 J2.3@81.08,14
3V8_MODEM: C3.1 C14.1 C15.1 C16.1 J2.1 L1.2 R1.1 TP4.1 | length 143.1
  F.Cu w0.25: R1.1@55.55,41.15 56.05,41.65 56.95,41.65 57.35,42.05 60.35,42.05 60.45,42.15 61.95,42.15 62.15,42.35 63.55,42.35
  F.Cu w0.5: 72.525,40.4 C16.1@72.525,43 ; C14.1@72.525,50 72.525,52.6
  F.Cu w1: TP4.1@32.62,4 34.172,2.448 48.516,2.448 49.412,3.343 49.412,7.012 48.322,8.102 v1(47.15,8.102) ; L1.2@64.76,43 L1.2@64.76,46 L1.2@64.76,48 ; J2.1@81.08,20 J2.1@81.08,20.58
  F.Cu w3: L1.2@64.76,43 C15.1@67.525,43 67.525,39.8 72.525,39.8 ; L1.2@64.76,48 C3.1@67.525,50 67.525,53.2 72.525,53.2 72.525,52.6 ; 72.525,40.4 72.525,39.8 ; J2.1@81.08,20.58 83.5,23 83.5,35.8 79.5,39.8 72.525,39.8
  B.Cu w0.3: 70.857,18.526 79.607,18.526 J2.1@81.08,20
  B.Cu w1: v1(47.15,8.102) 47.15,16.154 53.326,22.331 65.51,22.331 65.867,22.687 66.696,22.687 70.857,18.526
BOOT_3V3: C6.1 U4.4 | length 1.6
  F.Cu w0.5: 56.45,18.05 56.9,18.05 57.1,18.45 57.49,18.45 C6.1@57.8,18.45
BOOT_3V8: C4.1 U3.4 | length 1.6
  F.Cu w0.5: 56.45,46.05 56.9,46.05 57.1,46.45 57.49,46.45 C4.1@57.8,46.45
EN_AUX: J2.10 R11.1 U5.3 | length 15.6
  F.Cu w0.25: R11.1@65.49,11 65.49,12.004 66.536,13.05 U5.3@73.1,13.05 73.769,13.05 v1(74.172,13.453)
  B.Cu w0.25: v1(74.172,13.453) 74.172,13.004 76.353,10.823 77.903,10.823 J2.10@78.08,11
EN_MODEM: J2.9 R6.1 U3.9 | length 75.9
  F.Cu w0.2: v1(53.175,47.8) 53.175,45.925 U3.9@53.875,45.925
  F.Cu w0.25: v1(46.684,41.435) 47.425,41.435 R6.1@47.49,41.5
  B.Cu w0.25: v1(46.684,41.435) 46.684,43.122 51.361,47.8 v1@52.936,47.8 ; v1(53.175,47.8) v1@52.936,47.8 ; J2.9@78.08,14 79.188,12.892 83.424,12.892 87.491,16.959 87.491,18.832 56.367,49.956 54.14,49.956 52.936,48.752 v1@52.936,47.8
FAULT: J2.8 R12.2 TP8.1 U2.3 | length 78.3
  F.Cu w0.2: U2.3@41.8,37 42.7,37 v1(43.2,37.8)
  F.Cu w0.25: TP8.1@42.78,4 v1(42.78,5.368) 46.363,8.951 55.585,8.951 v1(56.287,9.653) ; R12.2@69.01,11 v1(69.648,11.638) 73.243,11.638 74.799,13.194 74.799,13.407 75.356,13.963 76.014,13.963 78.08,16.03 J2.8@78.08,17
  B.Cu w0.25: v1(42.78,5.368) 41.823,6.325 41.823,36.423 v1(43.2,37.8) ; v1(56.287,9.653) 57.396,10.762 68.772,10.762 v1(69.648,11.638)
FB_3V8: R1.2 R2.1 U3.6 | length 13.1
  F.Cu w0.2: U3.6@55.585,46.875 v1(55.585,48.8) ; v1(56.51,40.1) R1.2@56.51,41
  F.Cu w0.25: R1.2@56.51,41 R2.1@57.99,41
  B.Cu w0.2: v1(55.585,48.8) v1(56.51,40.1)
GND_DIGITAL: J2.4 NT2.1 | length 0.5
  F.Cu w0.25: NT2.1@76.1,11.48 76.6,11.48
GND_MIC: J2.6 NT3.1 | length 11.2
  F.Cu w0.5: v1(73.85,7.05) v1(74.547,7.447) NT3.1@75.1,8
  B.Cu w0.5: v1(73.85,7.05) 74.55,6.82 ; v1(74.547,7.447) 74.547,6.817 77.585,3.779 79.859,3.779 J2.6@81.08,5
GND_MODEM: J2.2 NT1.1 | length 0.5
  F.Cu w0.25: 74.6,19.88 NT1.1@75.1,19.88
  other v1: 74.15,16.45 74.4,17.25 73.85,17.85
GND_PWR: C2.2 C3.2 C5.2 C7.2 C8.2 C9.2 C10.2 C11.2 C12.2 C13.2 C14.2 C15.2 C16.2 C17.2 C18.2 C19.2 C20.2 C21.2 D1.2 J1.2 NT1.2 NT2.2 NT3.2 R2.2 R3.2 R4.2 R6.2 R7.2 R8.2 R11.2 U1.2 U2.1 U2.2 U2.7 U3.2 U4.2 U5.2 | length 62.7
  F.Cu w0.2: v1(44.9,36.5) U2.7@46.2,36.5
  F.Cu w0.25: 74.6,11.48 NT2.2@75.1,11.48
  F.Cu w0.3: U1.2@18.7,30 v1(20,30) ; U2.1@42.3,38 42.8,38.5 v1(44.4,38.5) ; v1(59.01,40.1) R2.2@59.01,41 ; R11.2@66.51,11 v1(66.51,12.1)
  F.Cu w0.45: 71.463,14.002 71.465,14 U5.2@73.1,14
  F.Cu w0.541: R7.2@50.51,13 51.689,11.821 v1@53.01,11.821
  F.Cu w0.6: R6.2@48.51,41.5 48.51,40.648 48.98,40.178 ; C2.2@48.98,38 C2.2@48.98,38.156 ; R3.2@51.01,41 51.01,40.799 50.389,40.178 48.98,40.178 ; R8.2@53.01,11 v1@53.01,11.821 ; R4.2@53.51,39 53.51,38.789 52.877,38.156 C2.2@48.98,38.156 ; U4.2@55,18 v1(55,18.075) ; U3.2@55,46 v1(55,46.075) ; C5.2@70.475,22 C18.2@70.475,15 71.463,14.012 71.463,14.002 ; C15.2@70.475,43 70.475,43.474 71.878,44.877 75.475,44.877 ; C3.2@70.475,50 70.475,49.526 71.894,48.108 75.475,48.108 ; C19.2@75.475,17.75 76.1,18.375 NT1.2@76.1,19.88 76.1,21.375 C17.2@75.475,22 ; C16.2@75.475,43 75.475,44.877 ; C14.2@75.475,50 75.475,48.108 ; C8.2@75.675,6 75.675,6.825 76.1,7.25 NT3.2@76.1,8 ; C2.2@48.98,38.156 48.98,40.178 ; 75.475,44.877 75.475,48.108
  F.Cu w1: v1(50.475,18) v1(52.35,18.775) ; v1(50.475,46) v1(52.35,46.775)
  other v1: 10.45,4.05 13.95,4.05 17.45,4.05 83.95,4.05 87.45,4.05 10.45,7.55 13.95,7.55 17.45,7.55 27.95,7.55 76.95,8.85 77.55,9.45 76.445,9.474 74.55,10.95 3.45,11.05 6.95,11.05 10.45,11.05 13.95,11.05 17.45,11.05 27.95,11.05 31.45,11.05 38.45,11.05 83.95,11.05 87.45,11.05 73.75,11.25 53.01,11.87 74.35,11.85 51.314,12.667 70.75,14 3.45,14.55 6.95,14.55 10.45,14.55 13.95,14.55 17.45,14.55 27.95,14.55 31.45,14.55 38.45,14.55 87.45,14.55 69.748,16.755 55,17.475 3.45,18.05 6.95,18.05 10.45,18.05 13.95,18.05 17.45,18.05 27.95,18.05 31.45,18.05 38.45,18.05 76.336,19.921 76.65,20.85 3.45,21.55 6.95,21.55 10.45,21.55 31.45,21.55 38.45,21.55 87.45,21.55 3.45,25.05 6.95,25.05 10.45,25.05 38.45,25.05 87.45,25.05 52,28 80.45,28.55 87.45,28.55 6.95,32.05 76.95,32.05 80.45,32.05 87.45,32.05 17.646,35.352 3.45,35.55 6.95,35.55 10.45,35.55 24.45,35.55 27.95,35.55 73.45,35.55 76.95,35.55 87.45,35.55 34.748,35.755 53.843,38.196 48.98,38.86 3.45,39.05 6.95,39.05 10.45,39.05 13.95,39.05 17.45,39.05 20.95,39.05 24.45,39.05 27.95,39.05 31.45,39.05 34.95,39.05 83.95,39.05 87.45,39.05 42.766,40.333 51.625,40.385 48.843,40.696 3.45,42.55 6.95,42.55 10.45,42.55 13.95,42.55 17.45,42.55 20.95,42.55 24.45,42.55 27.95,42.55 31.45,42.55 34.95,42.55 80.45,42.55 83.95,42.55 87.45,42.55 77.375,43 69.748,44.755 55,45.475 3.45,46.05 6.95,46.05 10.45,46.05 13.95,46.05 17.45,46.05 20.95,46.05 24.45,46.05 27.95,46.05 31.45,46.05 34.95,46.05 69.95,46.05 73.45,46.05 76.95,46.05 80.45,46.05 83.95,46.05 87.45,46.05 71.202,48.245 3.45,49.55 6.95,49.55 10.45,49.55 13.95,49.55 17.45,49.55 20.95,49.55 24.45,49.55 27.95,49.55 31.45,49.55 34.95,49.55 38.45,49.55 41.95,49.55 45.45,49.55 48.95,49.55 80.45,49.55 83.95,49.55 87.45,49.55 77.375,50 10.45,53.05 13.95,53.05 17.45,53.05 20.95,53.05 24.45,53.05 27.95,53.05 31.45,53.05 34.95,53.05 38.45,53.05 41.95,53.05 45.45,53.05 48.95,53.05 52.45,53.05 55.95,53.05 59.45,53.05 62.95,53.05 76.95,53.05 87.45,53.05 10.45,56.55 13.95,56.55 17.45,56.55 20.95,56.55 24.45,56.55 27.95,56.55 31.45,56.55 34.95,56.55 38.45,56.55 41.95,56.55 45.45,56.55 48.95,56.55 52.45,56.55 55.95,56.55 59.45,56.55 62.95,56.55 66.45,56.55 69.95,56.55 73.45,56.55 76.95,56.55 87.45,56.55
I2C2_SCL: J2.11 R13.2 TP9.1 U2.5 | length 74.4
  F.Cu w0.2: U2.5@41.8,36 42.7,36 v1(43.2,35.2)
  F.Cu w0.25: TP9.1@45.32,4 v1(45.32,5.4) ; R13.2@75.11,3.5 76.2,3.5 76.9,4.2 76.9,7.1 J2.11@78.08,8
  B.Cu w0.25: v1(43.2,35.2) 42.726,34.726 42.726,7.801 45.127,5.4 v1(45.32,5.4) 62,9.5 73.5,9.5 v1(76.9,6.1)
I2C2_SDA: J2.12 R14.2 TP10.1 U2.4 | length 81.1
  F.Cu w0.2: U2.4@41.8,36.5 v1(43.9,36.5)
  F.Cu w0.25: v1(46.994,5.075) 47.86,4.209 TP10.1@47.86,4 v1(47.86,7.1) ; R14.2@75.11,2 76.6,2 78.08,3.5 J2.12@78.08,5
  B.Cu w0.25: v1(43.9,36.5) 43.613,36.5 42.275,35.161 42.275,7.532 45.097,4.71 46.629,4.71 v1(46.994,5.075) ; v1(47.86,7.1) 61.8,10.2 74.2,10.2 78.08,6.32 J2.12@78.08,5
LM74700_VCAP: C1.1 U1.1 | length 3.2
  F.Cu w0.5: U1.1@18.7,30.95 C1.1@19.52,34
MODE_3V3: R8.1 R9.1 U4.7 | length 17.2
  F.Cu w0.2: U4.7@54.415,18.875 v1(54.415,21.3) ; v1(54.49,10.1) R9.1@54.49,11
  F.Cu w0.25: R8.1@52.05,10.85 52.55,10.35 54.25,10.35 54.35,10.25 v1@54.45,10.25
  B.Cu w0.2: v1(54.415,21.3) 54.2,19.5 54.2,16 v1(54.49,10.1)
MODE_3V8: R4.1 R5.1 U3.7 | length 17.8
  F.Cu w0.2: U3.7@54.415,46.875 v1(54.415,49.3) ; v1(54.99,38.1) R5.1@54.99,39
  F.Cu w0.5: R4.1@52.49,39 52.49,39.156 53.128,39.794 54.196,39.794 R5.1@54.99,39
  B.Cu w0.2: v1(54.415,49.3) 54.2,47.5 54.2,44 v1(54.99,38.1)
PG_3V8: R15.1 TP5.1 U3.5 | length 66.5
  F.Cu w0.2: U3.5@56,47.1 56,47.6 v1(56.6,48.2)
  F.Cu w0.201: U3.5@56,47.1 U3.5@56,46.9 56.01,46.9 U3.5@56.112,46.798
  F.Cu w0.25: TP5.1@35.16,4 41.686,10.526 v1(43.357,10.526) ; U3.5@56.112,46.798 56.175,46.735 U3.5@56.175,46.7 ; v1(59.857,38.867) R15.1@60.49,39.5
  B.Cu w0.25: v1(43.357,10.526) 43.357,33.978 47.031,37.652 53.156,37.652 53.363,37.444 58.435,37.444 v1(59.857,38.867) 59.857,44.943 v1(56.6,48.2)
